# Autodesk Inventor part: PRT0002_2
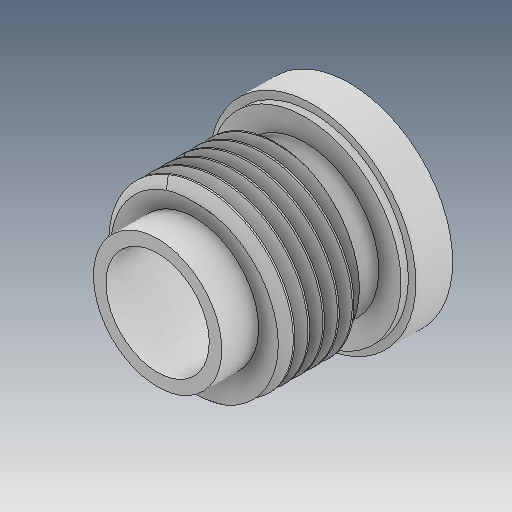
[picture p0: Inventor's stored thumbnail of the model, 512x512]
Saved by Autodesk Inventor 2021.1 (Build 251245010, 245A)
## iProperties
Created: 2019-04
Part Number: PRT0002_2
Material: Ogólny
Document SubType Name: Modeling
Designer: user
Density: 1 g/cm^3
Appearance: Domyślna
Author: user
Revision Number: ÈÎºÎ
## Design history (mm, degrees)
feature "ÊäÈë1"
node "Bryła1"
